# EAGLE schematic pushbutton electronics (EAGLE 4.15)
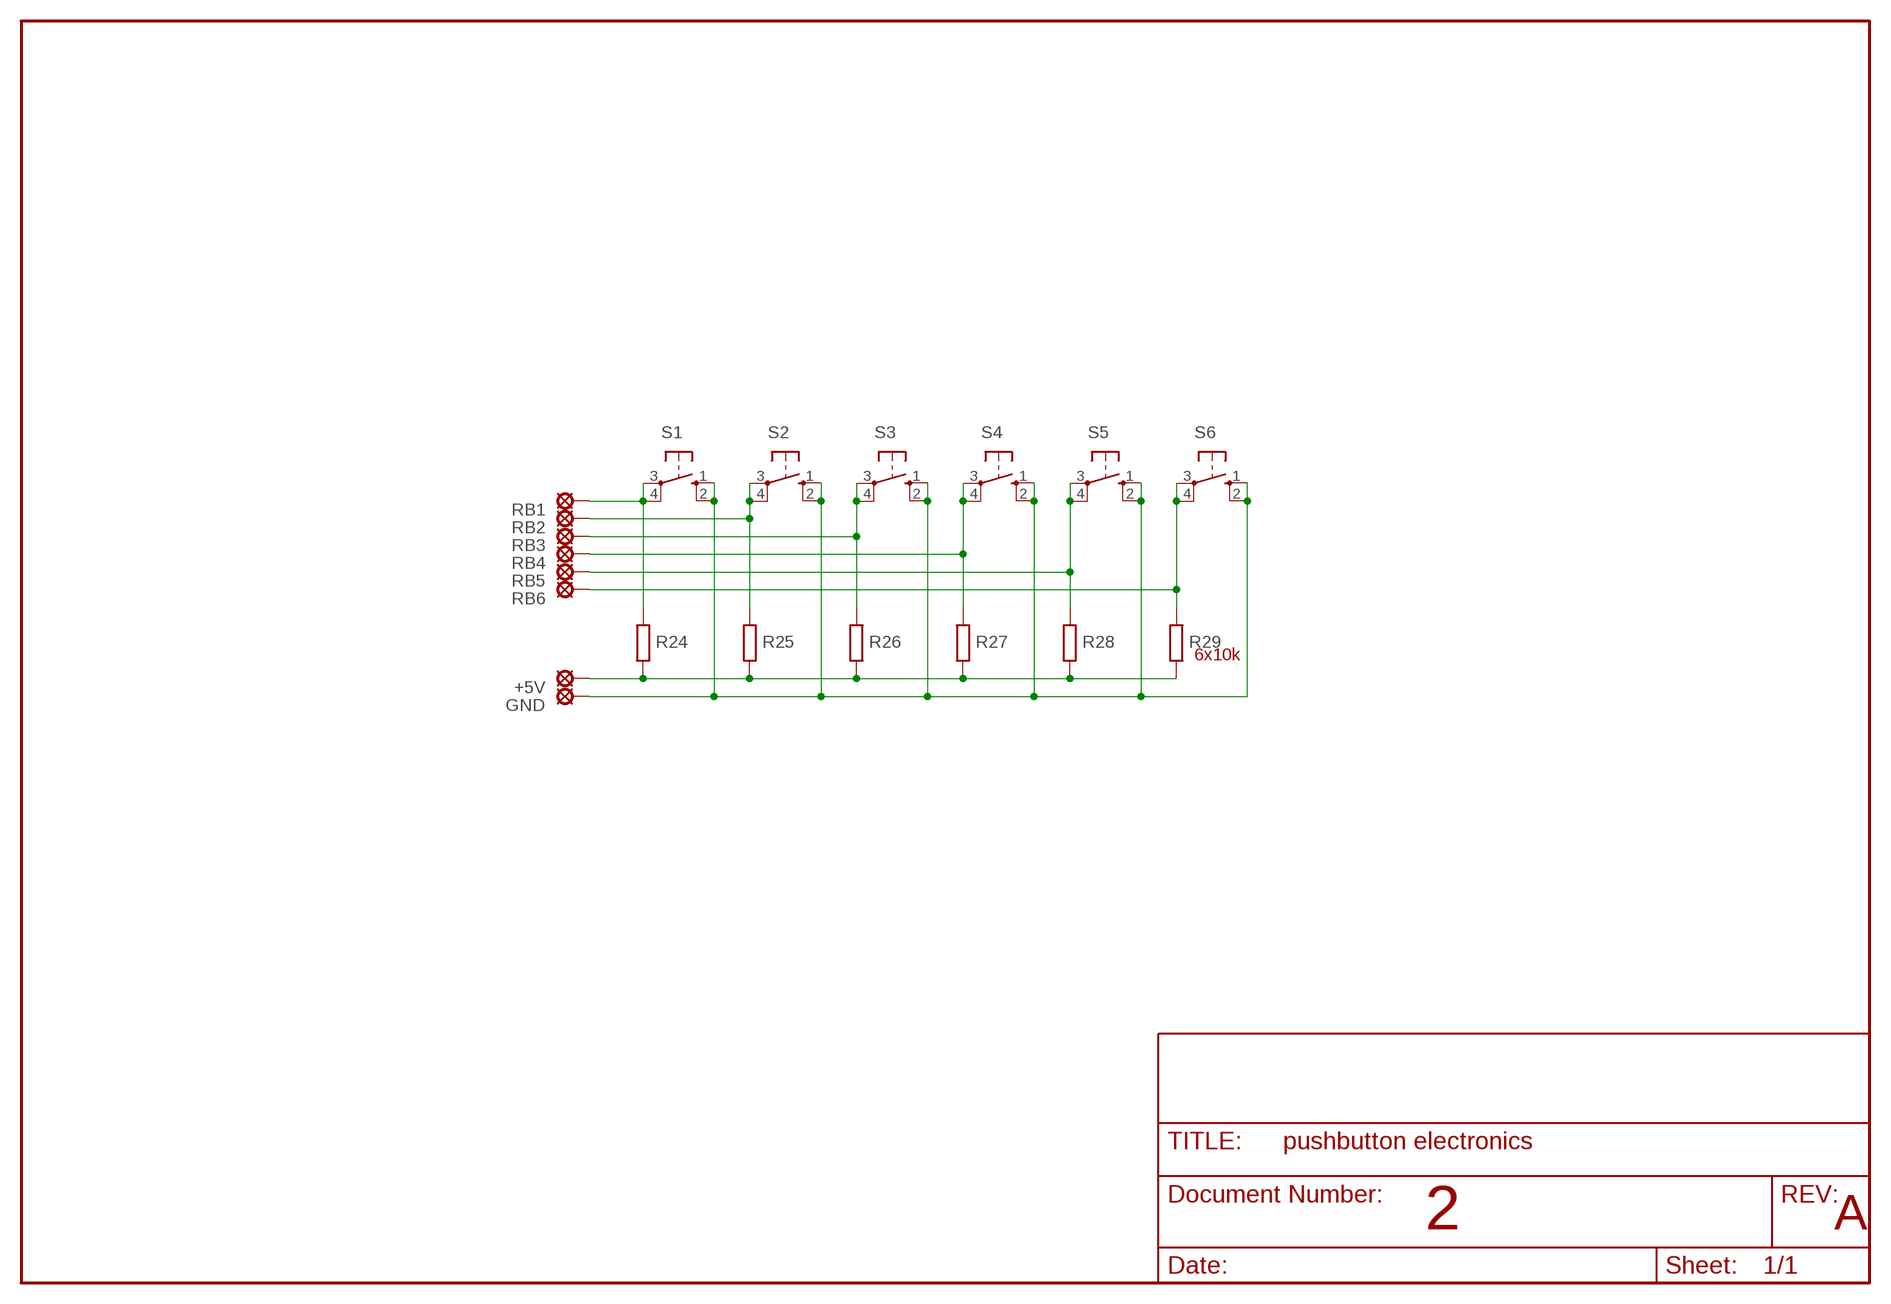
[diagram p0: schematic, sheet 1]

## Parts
+5V  LSP10  [LSP10]
GND  LSP10  [LSP10]
R24  R-EU_0309/10  [0309/10]
R25  R-EU_0309/10  [0309/10]
R26  R-EU_0309/10  [0309/10]
R27  R-EU_0309/10  [0309/10]
R28  R-EU_0309/10  [0309/10]
R29  R-EU_0309/10  [0309/10]
RB1  LSP10  [LSP10]
RB2  LSP10  [LSP10]
RB3  LSP10  [LSP10]
RB4  LSP10  [LSP10]
RB5  LSP10  [LSP10]
RB6  LSP10  [LSP10]
S1  40-XX  [B3F-40XX]
S2  40-XX  [B3F-40XX]
S3  40-XX  [B3F-40XX]
S4  40-XX  [B3F-40XX]
S5  40-XX  [B3F-40XX]
S6  40-XX  [B3F-40XX]

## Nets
N$1: R24.2 RB1.MP S1.3(P) S1.4(P1)
N$2: R25.2 RB2.MP S2.3(P) S2.4(P1)
N$3: R26.2 RB3.MP S3.3(P) S3.4(P1)
N$4: R27.2 RB4.MP S4.3(P) S4.4(P1)
N$5: R28.2 RB5.MP S5.3(P) S5.4(P1)
N$6: R29.2 RB6.MP S6.3(P) S6.4(P1)
N$7: +5V.MP R24.1 R25.1 R26.1 R27.1 R28.1 R29.1
N$8: GND.MP S1.1(S) S1.2(S1) S2.1(S) S2.2(S1) S3.1(S) S3.2(S1) S4.1(S) S4.2(S1) S5.1(S) S5.2(S1) S6.1(S) S6.2(S1)

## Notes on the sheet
- 6x10k
- 2 | A

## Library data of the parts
+5V GND RB1-RB6 = solpad:LSP10: SOLDER PAD
R24-R29 = rcl:R-EU_: RESISTOR, European symbol
S1-S6 = switch-omron:40-XX: OMRON SWITCH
